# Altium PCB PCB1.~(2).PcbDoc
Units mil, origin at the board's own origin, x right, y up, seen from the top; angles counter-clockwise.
Board outline 6000 x 4000 mil, 2 copper layers (Top Layer, Bottom Layer); 61 components, 56 nets, 209 pads, 0 vias.
Unrouted connection lines stored in the file: 152.
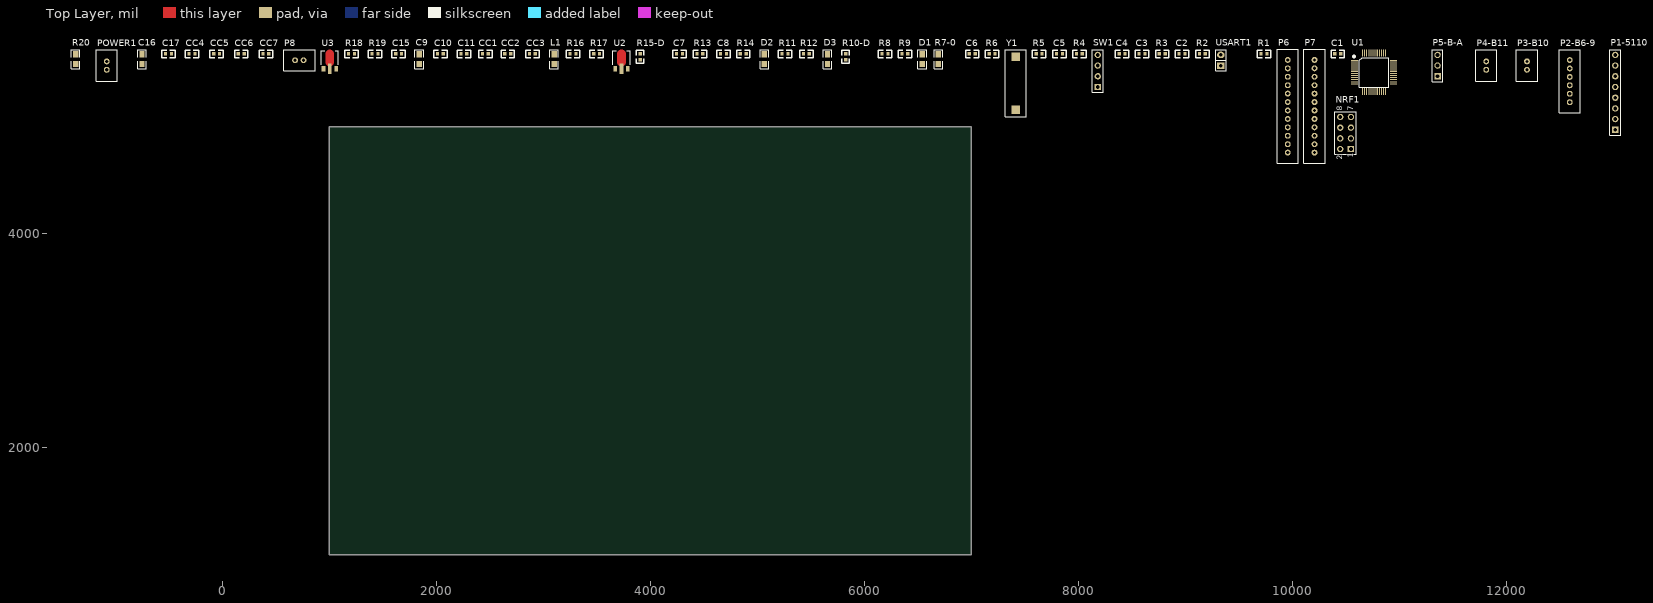
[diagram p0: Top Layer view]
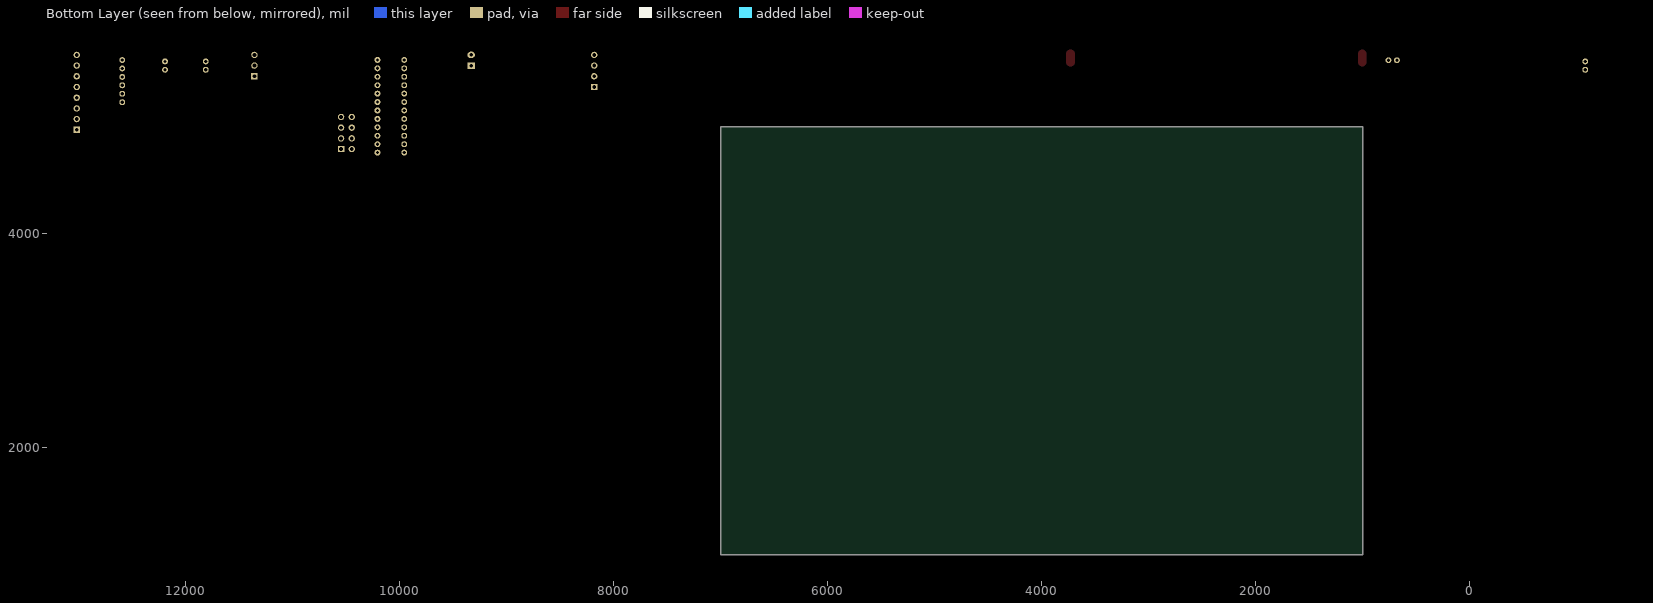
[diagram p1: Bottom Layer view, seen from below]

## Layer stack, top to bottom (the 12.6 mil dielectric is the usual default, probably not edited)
Top Solder: solder mask 0.4, Solder Resist, Dk 3.5
Top Layer: signal copper 1.4
Dielectric 1: dielectric 12.6, FR-4, Dk 4.8
Bottom Layer: signal copper 1.4
Bottom Solder: solder mask 0.4, Solder Resist, Dk 3.5

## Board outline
1000,1000 7000,1000 7000,5000 1000,5000

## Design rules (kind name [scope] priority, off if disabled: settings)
Clearance [All] p1: gap=7
PolygonConnect [All] p1: connectstyle=Relief reliefconductorwidth=10 reliefentries=4 polygonreliefangle="90 Angle" airgapwidth=10
RoutingVias [All] p1: holewidth=28 width=50 viastyle="Through Hole" minholewidth=28 minwidth=50 maxholewidth=28 maxwidth=50
SolderMaskExpansion [All] p1: expansion=4
UnpouredPolygon [All] p1: allowunpoured=FALSE
Width [All] p1: maxlimit=10 minlimit=10 preferedwidth=10
29 further rules are at their usual default settings.

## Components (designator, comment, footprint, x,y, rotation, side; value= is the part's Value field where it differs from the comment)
C1 "cap" 0603c 10395,5680 r0 top
C2 "cap" 0603c 8940,5680 r0 top
C3 "cap" 0603c 8565,5680 r0 top
C4 "cap" 0603c 8380,5680 r0 top
C5 "cap" 0603c 7795,5680 r0 top
C6 "cap" 0603c 6980,5680 r0 top
C7 "cap" 0603c 4245,5680 r0 top
C8 "cap" 0603c 4655,5680 r0 top
C9 "cap" 0805 1840,5585 r90 top
C10 "cap" 0603c 2010,5680 r0 top
C11 "cap" 0603c 2230,5680 r0 top
C15 "cap" 0603c 1620,5680 r0 top
C16 "cap" 0805 -750,5585 r90 top
C17 "cap" 0603c -530,5680 r0 top
CC1 "cap" 0603c 2430,5680 r0 top
CC2 "cap" 0603c 2640,5680 r0 top
CC3 "cap" 0603c 2870,5680 r0 top
CC4 "cap" 0603c -310,5680 r0 top
CC5 "cap" 0603c -80,5680 r0 top
CC6 "cap" 0603c 150,5680 r0 top
CC7 "cap" 0603c 380,5680 r0 top
D1 "LED0" 0805 6540,5585 r90 top
D2 "LED0" 0805 5065,5585 r90 top
D3 "LED0" 0805 5655,5585 r90 top
L1 "Inductor" 0805 3100,5585 r90 top
NRF1 "Header 4X2" HDR2X4 10545,4790 r90 top
P1-5110 "Header 8" HDR1X8 13015,4970 r90 top
P2-B6-9 "Header 6" 6p 12590,5425 r90 top
P3-B10 "Header 2" 2p 12190,5570 r90 top
P4-B11 "Header 2" 2p 11810,5570 r90 top
P5-B-A "Header 3" HDR1X3 11355,5470 r90 top
P6 "Header 12" 12p 9955,5190 r90 top
P7 "Header 12" 12p 10205,5190 r90 top
P8 "Header 2" 2p 720,5620 r0 top
POWER1 "CON2" 2p -1080,5570 r90 top
R1 "res" 0603c 9705,5680 r0 top
R2 "10K" 0603c 9130,5680 r0 top
R3 "10K" 0603c 8755,5680 r0 top
R4 "10K" 0603c 7980,5680 r0 top
R5 "res" 0603c 7605,5680 r0 top
R6 "1K" 0603c 7165,5680 r0 top
R7-0 "0R" 0805 6690,5585 r90 top
R8 "10K" 0603c 6165,5680 r0 top
R9 "10K" 0603c 6350,5680 r0 top
R10-D "res" 0603c 5825,5625 r90 top
R11 "1K" 0603c 5230,5680 r0 top
R12 "1K" 0603c 5430,5680 r0 top
R13 "10K" 0603c 4435,5680 r0 top
R14 "10K" 0603c 4840,5680 r0 top
R15-D "res" 0603c 3905,5625 r90 top
R16 "10K" 0603c 3250,5680 r0 top
R17 "10K" 0603c 3470,5680 r0 top
R18 "10K" 0603c 1180,5680 r0 top
R19 "10K" 0603c 1400,5680 r0 top
R20 "0R" 0805 -1370,5585 r90 top
SW1 "Header 4" HDR1X4 8180,5370 r90 top
U1 "STM32F103C8T6" LQFP48S 10580,5615 r0 top
U2 "XC6203E" SOT-89 3670,5540 r0 top
U3 "XC6203E" SOT-89 945,5540 r0 top
USART1 "CON2" SIP2 9330,5620 r90 top
Y1 "5032xtal" 晶振 7415,5405 r90 top

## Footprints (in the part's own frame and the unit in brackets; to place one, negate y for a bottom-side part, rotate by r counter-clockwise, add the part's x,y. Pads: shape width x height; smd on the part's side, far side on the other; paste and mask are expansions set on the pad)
2p [mil]
  round 55 hole 30: 1(-39.37,0) 2(39.37,0)
  silkscreen extent -148,-98 148,98
6p [mil]
  round 55 hole 30: 1(-196.85,0) 2(-118.11,0) 3(-39.37,0) 4(39.37,0) 5(118.11,0) 6(196.85,0)
  silkscreen extent -295,-98 295,98
12p [mil]
  round 55 hole 30: 1(-433.07,0) 2(-354.33,0) 3(-275.59,0) 4(-196.85,0) 5(-118.11,0) 6(-39.37,0) 7(39.37,0) 8(118.11,0) 9(196.85,0) 10(275.59,0) 11(354.33,0) 12(433.07,0)
  silkscreen extent -531,-98 531,98
0603c [mil]
  rect 30x30 smd: 1(0,0) 2(55,0)
  silkscreen extent -35,-35 90,35
0805 [mil]
  rect 60x50 smd: 1(0,0) 2(90,0)
  silkscreen extent -45,-40 135,40
HDR1X3 [mm] "Connector; Header; 3 Position"
  rect 1.5x1.5 hole 0.9: 1(0,0)
  round 1.5 hole 0.9: 2(2.54,0) 3(5.08,0)
  silkscreen extent -1.27,-1.27 6.35,1.27
HDR1X4 [mm] "Connector; Header; 4 Position"
  rect 1.5x1.5 hole 0.9: 1(0,0)
  round 1.5 hole 0.9: 2(2.54,0) 3(5.08,0) 4(7.62,0)
  silkscreen extent -1.27,-1.27 8.89,1.27
HDR1X8 [mm] "Connector; Header; 8 Position"
  rect 1.5x1.5 hole 0.9: 1(0,0)
  round 1.5 hole 0.9: 2(2.54,0) 3(5.08,0) 4(7.62,0) 5(10.16,0) 6(12.7,0) 7(15.24,0) 8(17.78,0)
  silkscreen extent -1.27,-1.27 19.05,1.27
HDR2X4 [mm] "Connector; Header; 4x2 Position"
  rect 1.5x1.5 hole 0.9: 1(0,0)
  round 1.5 hole 0.9: 2(0,2.54) 3(2.54,0) 4(2.54,2.54) 5(5.08,0) 6(5.08,2.54) 7(7.62,0) 8(7.62,2.54)
  silkscreen extent -1.27,-1.27 8.89,3.81
LQFP48S [mil] "DPIN-0.5"
  rect 65x10 smd: 1(0.42,0.29) 2(0.42,-19.39) 3(0.42,-39.08) 4(0.42,-58.76) 5(0.42,-78.45) 6(0.42,-98.13) 7(0.42,-117.82) 8(0.42,-137.5) 9(0.42,-157.19) 10(0.42,-176.87) 11(0.42,-196.56) 12(0.42,-216.24) 25(362.63,-216.24) 26(362.63,-196.56) 27(362.63,-176.87) 28(362.63,-157.19) 29(362.63,-137.5) 30(362.63,-117.82) 31(362.63,-98.13) 32(362.63,-78.45) 33(362.63,-58.76) 34(362.63,-39.08) 35(362.63,-19.39) 36(362.63,0.29)
  rect 10x65 smd: 13(73.26,-289.08) 14(92.94,-289.08) 15(112.63,-289.08) 16(132.31,-289.08) 17(152,-289.08) 18(171.68,-289.08) 19(191.37,-289.08) 20(211.05,-289.08) 21(230.74,-289.08) 22(250.42,-289.08) 23(270.11,-289.08) 24(289.79,-289.08) 37(289.79,73.13) 38(270.11,73.13) 39(250.42,73.13) 40(230.74,73.13) 41(211.05,73.13) 42(191.37,73.13) 43(171.68,73.13) 44(152,73.13) 45(132.31,73.13) 46(112.63,73.13) 47(92.94,73.13) 48(73.26,73.13)
  silkscreen extent -10,-246 319,46
SIP2 [mil]
  rect 60x70 hole 32: 1(-50,0)
  oval 60x70 hole 32: 2(50,0)
  silkscreen extent -100,-50 100,50
SOT-89 [mil]
  rect 34x50 smd: 1(0,0) 3(120,0)
  rect 34x100 smd: 2(60,0)
  Top Layer lines w80: 60,60 60,140
  silkscreen extent -20,40 140,170
晶振 [mm]
  rect 2x2 smd: 1(-6.25,0) 2(6.25,0)
  silkscreen extent -8,-2.5 8,2.5

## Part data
D1 D2 D3: "Typical INFRARED GaAs LED"
NRF1: "Header, 4-Pin, Dual row"
P1-5110: "Header, 8-Pin"
P2-B6-9: "Header, 6-Pin"
P3-B10 P4-B11 P8: "Header, 2-Pin"
P5-B-A: "Header, 3-Pin"
P6 P7: "Header, 12-Pin"
R2 R3 R4 R6 R7-0 R8 R9 R11 R12 R13 R14 R16 R17 R18 R19 R20: library part RES
SW1: "Header, 4-Pin"
U2 U3: library part XC6203

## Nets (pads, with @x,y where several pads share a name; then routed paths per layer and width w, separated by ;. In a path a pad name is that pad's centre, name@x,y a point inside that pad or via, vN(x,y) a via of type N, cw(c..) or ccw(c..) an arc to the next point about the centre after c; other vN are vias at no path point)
3.3_2: CC4.2 CC5.2 CC6.2 CC7.2 NRF1.2 R6.2 R15-D.1 U3.3
3.3V: C1.2 C2.2 C4.2 C11.2 CC1.2 CC2.2 CC3.2 L1.1 P1-5110.6 P1-5110.7 P6.4 P6.7 P7.4 P7.7 R2.2 R7-0.2 R8.2 R9.2 R10-D.1 SW1.4 U1.24 U1.36 U1.48 U2.3
ADC_KEY_L: C7.2 R11.2 U1.18
ADC_KEY_R: C8.2 R12.2 U1.19
ADC_PITCH: P7.5 U1.12
ADC_POWER: R3.1 R4.2 U1.14
ADC_ROLL: P7.8 U1.13
ADC_THR: P6.5 U1.10
ADC_YAW: P6.8 U1.11
AGND: C7.1 C8.1 P6.2 P6.6 P6.9 P6.11 P7.2 P7.6 P7.9 P7.11 R4.1 R20.2 U1.8
AVDD: C15.2 L1.2 U1.9
BAT: P8.1 POWER1.2 R3.2
BOOT0: R5.2 U1.44
BOOT1: R1.1 U1.20
CE: P1-5110.2 U1.16
CLK: P1-5110.5 U1.32
DC: P1-5110.3 U1.17
DGND: C1.1 C2.1 C3.1 C4.1 C5.1 C6.1 C9.1 C10.1 C11.1 C15.1 C16.1 C17.1 CC1.1 CC2.1 CC3.1 CC4.1 CC5.1 CC6.1 CC7.1 D1.2 D2.2 NRF1.1 P1-5110.8 P2-B6-9.2 P2-B6-9.5 P3-B10.2 P4-B11.2 POWER1.1 R1.2 R5.1 R20.1 SW1.1 U1.23 U1.35 U1.47 U2.1 U3.1
DIN: P1-5110.4 U1.29
KEY_1: P6.1 R8.1 R11.1 R13.2
KEY_2: P6.3 R13.1 R16.2
KEY_3: P6.10 R16.1 R18.2
KEY_4: P6.12 R18.1
KEY_5: P7.1 R9.1 R12.1 R14.2
KEY_6: P7.3 R14.1 R17.2
KEY_7: P7.10 R17.1 R19.2
KEY_8: P7.12 R19.1
KEYY: U1.38
LED0: D3.2 U1.2
MISO: NRF1.7 U1.27
MOSI: NRF1.6 U1.28
NetC5_2: C5.2 U1.5 Y1.2
NetC6_2: C6.2 U1.6 Y1.1
NetD1_1: D1.1 R10-D.2
NetD2_1: D2.1 R15-D.2
NetD3_1: D3.1 R6.1
NetR7-0_1: R7-0.1 U1.1
PA12: P5-B-A.1 U1.33
PB3: P5-B-A.3 U1.39
PB4: P5-B-A.2 U1.40
PB6: P2-B6-9.1 U1.42
PB7: P2-B6-9.3 U1.43
PB8: P2-B6-9.4 U1.45
PB9: P2-B6-9.6 U1.46
PB10: P3-B10.1 U1.21
PB11: P4-B11.1 U1.22
RST: C3.2 P1-5110.1 R2.1 U1.7 U1.15
SWCLK: SW1.3 U1.37
SWDIO: SW1.2 U1.34
USART1_RX: U1.31 USART1.2
USART1_TX: U1.30 USART1.1
VCC: C9.2 C10.2 C16.2 C17.2 P8.2 U2.2 U3.2
W_CE: NRF1.3 U1.41
W_CSN: NRF1.4 U1.25
W_IRQ: NRF1.8 U1.3
W_SCK: NRF1.5 U1.26
pads on no net: U1.4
